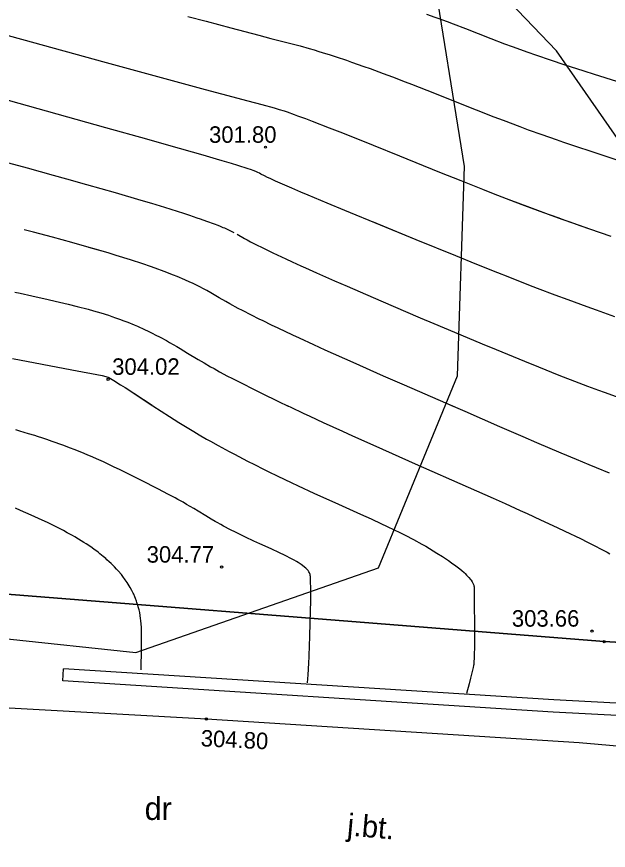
# Model space of a CAD drawing. Extents: x 7477803 to 7478145, y 5500698 to 5500984.
# Drawn here: x 7477958.24 to 7477982.63, y 5500809.46 to 5500843.86 of the extents above; entities that cross this region are included whole.
import ezdxf

# ---------------------------------------------------------------- set-up
doc = ezdxf.new("R2010")
doc.units = 0
for name, color, linetype in [('203-Punkt załamania granicy działki nie stabilizowany', 7, 'Continuous'), ('gr_dzialki', 7, 'Continuous'), ('gr_klasy', 7, 'Continuous'), ('jezdnia', 7, 'Continuous'), ('opis_uzytek', 7, 'Continuous'), ('opisy_drog', 7, 'Continuous'), ('pkt_wys', 7, 'Continuous'), ('rowy', 7, 'Continuous'), ('uwagi_projektanci', 7, 'Continuous'), ('warst_ciagla', 7, 'Continuous'), ('warst_pogrub', 7, 'Continuous'), ('warst_przeryw', 7, 'Continuous')]:
    doc.layers.add(name, color=color, linetype=linetype)

# ---------------------------------------------------------------- blocks, each defined once
blk = doc.blocks.new('203')
blk.add_circle((0, 0), 0.045)
blk = doc.blocks.new('801_1')
at = {"layer": 'pkt_wys'}
blk.add_circle((0, 0), 0.045, dxfattribs=at)
blk.add_circle((0, 0), 0.045, dxfattribs=at)
blk = doc.blocks.new('801_3')
at = {"layer": 'pkt_wys'}
blk.add_circle((0, 0), 0.045, dxfattribs=at)
blk.add_circle((0, 0), 0.045, dxfattribs=at)
blk = doc.blocks.new('801_5')
at = {"layer": 'pkt_wys'}
blk.add_circle((0, 0), 0.05, dxfattribs=at)
blk.add_circle((0, 0), 0.05, dxfattribs=at)

msp = doc.modelspace()

# ---------------------------------------------------------------- linework, layer by layer
at = {"layer": 'gr_dzialki'}
for points in [[(7477982.46, 5500818.07), (7477950.55, 5500820.61)], [(7478006.38, 5500816.66), (7477982.46, 5500818.07)]]:
    msp.add_lwpolyline(points, dxfattribs=at)
at = {"layer": 'gr_klasy'}
for points in [[(7477980.49, 5500842.45), (7477927.08, 5500898.2)], [(7477998.08, 5500817.16), (7477980.49, 5500842.45)], [(7477950.55, 5500820.61), (7477982.46, 5500818.07)], [(7477982.46, 5500818.07), (7477998.08, 5500817.16)]]:
    msp.add_lwpolyline(points, dxfattribs=at)
at = {"layer": 'jezdnia'}
msp.add_lwpolyline([(7477875.926, 5500787.879), (7477876.814, 5500788.851), (7477888.353, 5500798.574), (7477893.52, 5500801.94), (7477899.965, 5500805.717), (7477906.333, 5500808.394), (7477918.837, 5500813.137), (7477925.266, 5500814.534), (7477933.655, 5500815.503), (7477941.064, 5500815.881), (7477951.515, 5500815.693), (7477966.065, 5500814.879), (7477981.427, 5500813.916), (7477996.758, 5500812.562), (7478008.149, 5500811.845)], dxfattribs=at)
at = {"layer": 'rowy'}
for points in [[(7477990.382, 5500814.641), (7477980.361, 5500815.165), (7477960.146, 5500816.452), (7477960.178, 5500816.951)], [(7477990.411, 5500815.14), (7477980.39, 5500815.664), (7477960.178, 5500816.951)]]:
    msp.add_lwpolyline(points, dxfattribs=at)
at = {"layer": 'uwagi_projektanci'}
msp.add_lwpolyline([(7477973.16, 5500821.11), (7477976.42, 5500829.04), (7477976.7, 5500837.68), (7477975.34, 5500846.14), (7477969.75, 5500849.6), (7477966.4, 5500846.83), (7477944.18, 5500852.96), (7477931.39, 5500854.5), (7477929.49, 5500844.63), (7477930.21, 5500832.13), (7477946.85, 5500819.35), (7477963.16, 5500817.62)], close=True, dxfattribs=at)
at = {"layer": 'warst_ciagla'}
for points in [[(7477965.304, 5500843.867), (7477966.053, 5500843.666), (7477967.068, 5500843.396), (7477968.222, 5500843.092), (7477968.714, 5500842.964), (7477969.549, 5500842.749), (7477969.928, 5500842.648), (7477970.305, 5500842.543), (7477970.5, 5500842.486), (7477970.7, 5500842.426), (7477970.979, 5500842.34), (7477971.122, 5500842.294), (7477971.418, 5500842.198), (7477971.832, 5500842.059), (7477972.047, 5500841.985), (7477972.549, 5500841.808), (7477972.811, 5500841.714), (7477973.17, 5500841.582), (7477973.354, 5500841.514), (7477973.732, 5500841.373), (7477974.254, 5500841.174), (7477974.523, 5500841.069), (7477975.147, 5500840.824), (7477977.183, 5500840.013), (7477977.915, 5500839.727), (7477978.291, 5500839.583), (7477978.978, 5500839.325), (7477979.335, 5500839.195), (7477979.891, 5500838.994), (7477980.48, 5500838.787), (7477980.789, 5500838.68), (7477981.439, 5500838.459), (7477981.782, 5500838.344), (7477982.322, 5500838.165), (7477983.358, 5500837.827)], [(7477982.895, 5500831.478), (7477982.144, 5500831.744), (7477981.761, 5500831.882), (7477981.242, 5500832.072), (7477980.979, 5500832.169), (7477980.446, 5500832.368), (7477979.72, 5500832.644), (7477979.352, 5500832.786), (7477978.507, 5500833.117), (7477978.077, 5500833.287), (7477977.211, 5500833.634), (7477976.348, 5500833.984), (7477974.706, 5500834.656), (7477971.769, 5500835.866), (7477971.039, 5500836.169), (7477970.26, 5500836.494), (7477969.953, 5500836.623), (7477969.591, 5500836.777), (7477969.102, 5500836.99), (7477968.911, 5500837.077), (7477968.686, 5500837.18), (7477968.588, 5500837.226), (7477968.456, 5500837.29), (7477968.312, 5500837.363), (7477968.254, 5500837.395), (7477968.181, 5500837.434), (7477968.135, 5500837.456), (7477968.038, 5500837.496), (7477967.887, 5500837.55), (7477967.785, 5500837.584), (7477967.355, 5500837.719), (7477967.103, 5500837.795), (7477966.708, 5500837.913), (7477966.486, 5500837.978), (7477965.926, 5500838.141), (7477964.513, 5500838.547), (7477963.608, 5500838.803), (7477961.921, 5500839.278), (7477957.904, 5500840.402)], [(7477982.895, 5500831.478), (7477982.144, 5500831.744), (7477981.761, 5500831.882), (7477981.242, 5500832.072), (7477980.979, 5500832.169), (7477980.446, 5500832.368), (7477979.72, 5500832.644), (7477979.352, 5500832.786), (7477978.507, 5500833.117), (7477978.077, 5500833.287), (7477977.211, 5500833.634), (7477976.348, 5500833.984), (7477974.706, 5500834.656), (7477972.95, 5500835.378)], [(7477976.282, 5500827.755), (7477975.934, 5500827.906), (7477974.235, 5500828.648), (7477973.369, 5500829.029), (7477972.113, 5500829.585), (7477970.965, 5500830.102), (7477970.493, 5500830.318), (7477969.9, 5500830.591), (7477969.62, 5500830.721), (7477969.028, 5500831.001), (7477968.752, 5500831.134), (7477968.404, 5500831.302), (7477968.239, 5500831.383), (7477967.928, 5500831.539), (7477967.549, 5500831.732), (7477967.375, 5500831.823), (7477967.023, 5500832.013), (7477966.866, 5500832.1), (7477966.584, 5500832.263), (7477966.245, 5500832.461), (7477966.079, 5500832.555), (7477965.909, 5500832.648), (7477965.821, 5500832.695), (7477965.682, 5500832.765), (7477965.486, 5500832.86), (7477965.384, 5500832.907), (7477965.169, 5500833.003), (7477964.863, 5500833.133), (7477964.701, 5500833.198), (7477964.317, 5500833.347), (7477963.95, 5500833.482), (7477963.754, 5500833.551), (7477963.443, 5500833.657), (7477962.927, 5500833.826), (7477962.338, 5500834.009), (7477962.012, 5500834.107), (7477961.379, 5500834.293), (7477961.043, 5500834.39), (7477960.521, 5500834.537), (7477959.722, 5500834.756), (7477958.935, 5500834.965), (7477958.556, 5500835.063)], [(7477982.683, 5500825.027), (7477982.143, 5500825.244), (7477981.841, 5500825.368), (7477981.32, 5500825.586), (7477980.695, 5500825.851), (7477979.692, 5500826.279), (7477979.118, 5500826.526), (7477978.166, 5500826.937), (7477976.727, 5500827.562), (7477975.934, 5500827.906), (7477974.235, 5500828.648), (7477973.369, 5500829.029), (7477972.113, 5500829.585), (7477970.965, 5500830.102), (7477970.493, 5500830.318), (7477969.9, 5500830.591), (7477969.62, 5500830.721), (7477969.028, 5500831.001), (7477968.752, 5500831.134), (7477968.404, 5500831.302), (7477968.239, 5500831.383), (7477967.928, 5500831.539), (7477967.549, 5500831.732), (7477967.375, 5500831.823), (7477967.023, 5500832.013), (7477966.866, 5500832.1), (7477966.584, 5500832.263), (7477966.245, 5500832.461), (7477966.079, 5500832.555), (7477965.909, 5500832.648), (7477965.821, 5500832.695), (7477965.682, 5500832.765), (7477965.486, 5500832.86), (7477965.384, 5500832.907), (7477965.169, 5500833.003), (7477964.863, 5500833.133), (7477964.701, 5500833.198), (7477964.317, 5500833.347), (7477963.95, 5500833.482), (7477963.754, 5500833.551), (7477963.443, 5500833.657), (7477962.927, 5500833.826), (7477962.338, 5500834.009), (7477962.012, 5500834.107), (7477961.218, 5500834.339)], [(7477958.075, 5500829.751), (7477960.518, 5500829.287), (7477961.765, 5500829.047), (7477961.913, 5500829.017), (7477961.961, 5500829.004), (7477962.019, 5500828.983), (7477962.046, 5500828.97), (7477962.108, 5500828.934), (7477962.247, 5500828.848), (7477962.527, 5500828.67), (7477962.708, 5500828.553), (7477963.857, 5500827.806), (7477964.542, 5500827.36), (7477964.925, 5500827.118), (7477965.334, 5500826.865), (7477965.548, 5500826.737), (7477965.769, 5500826.607), (7477966.072, 5500826.431), (7477966.229, 5500826.343), (7477966.55, 5500826.164), (7477966.995, 5500825.922), (7477967.226, 5500825.8), (7477967.763, 5500825.521), (7477968.041, 5500825.38), (7477968.421, 5500825.189), (7477968.616, 5500825.093), (7477969.014, 5500824.899), (7477969.562, 5500824.637), (7477969.843, 5500824.505), (7477970.495, 5500824.203), (7477971.512, 5500823.743), (7477972.417, 5500823.335), (7477972.857, 5500823.134), (7477973.281, 5500822.937), (7477973.486, 5500822.84), (7477973.837, 5500822.671), (7477974.006, 5500822.588), (7477974.252, 5500822.464), (7477974.605, 5500822.28), (7477974.941, 5500822.098), (7477975.103, 5500822.006), (7477975.417, 5500821.821), (7477975.569, 5500821.728), (7477975.792, 5500821.586), (7477976.048, 5500821.415), (7477976.171, 5500821.329), (7477976.347, 5500821.199), (7477976.511, 5500821.069), (7477976.588, 5500821.005), (7477976.684, 5500820.92), (7477976.729, 5500820.878), (7477976.792, 5500820.815), (7477976.879, 5500820.722), (7477976.945, 5500820.641), (7477976.974, 5500820.601), (7477977.013, 5500820.542), (7477977.046, 5500820.485), (7477977.06, 5500820.457), (7477977.082, 5500820.401), (7477977.09, 5500820.374), (7477977.1, 5500820.333)], [(7477958.075, 5500829.751), (7477960.518, 5500829.287), (7477961.765, 5500829.047), (7477961.913, 5500829.017), (7477961.961, 5500829.004), (7477962.019, 5500828.983), (7477962.046, 5500828.97), (7477962.108, 5500828.934), (7477962.247, 5500828.848), (7477962.527, 5500828.67), (7477962.708, 5500828.553), (7477963.832, 5500827.822)], [(7477977.1, 5500820.333), (7477977.109, 5500819.435), (7477977.112, 5500818.942), (7477977.114, 5500818.179), (7477977.113, 5500817.894), (7477977.106, 5500817.482), (7477977.102, 5500817.384), (7477977.094, 5500817.234), (7477977.084, 5500817.131), (7477977.076, 5500817.081), (7477977.059, 5500817.002), (7477976.954, 5500816.569), (7477976.892, 5500816.326), (7477976.792, 5500815.937)]]:
    msp.add_lwpolyline(points, dxfattribs=at)
at = {"layer": 'warst_pogrub'}
msp.add_lwpolyline([(7477963.374, 5500816.904), (7477963.375, 5500817.164), (7477963.381, 5500817.542), (7477963.385, 5500817.745), (7477963.393, 5500818.195), (7477963.391, 5500818.43), (7477963.383, 5500818.668), (7477963.375, 5500818.789), (7477963.36, 5500818.949), (7477963.35, 5500819.029), (7477963.333, 5500819.149), (7477963.312, 5500819.268), (7477963.299, 5500819.327), (7477963.286, 5500819.386), (7477963.267, 5500819.465), (7477963.256, 5500819.504), (7477963.234, 5500819.582), (7477963.201, 5500819.684), (7477963.183, 5500819.736), (7477963.14, 5500819.85), (7477963.109, 5500819.926), (7477963.065, 5500820.026), (7477963.041, 5500820.076), (7477962.992, 5500820.175), (7477962.92, 5500820.306), (7477962.882, 5500820.371), (7477962.79, 5500820.516), (7477962.717, 5500820.623), (7477962.612, 5500820.765), (7477962.556, 5500820.835), (7477962.424, 5500820.992), (7477962.363, 5500821.06), (7477962.277, 5500821.152), (7477962.233, 5500821.197), (7477962.131, 5500821.298), (7477962.061, 5500821.365), (7477961.963, 5500821.453), (7477961.914, 5500821.497), (7477961.811, 5500821.584), (7477961.67, 5500821.699), (7477961.596, 5500821.756), (7477961.426, 5500821.883), (7477961.293, 5500821.977), (7477961.109, 5500822.101), (7477961.015, 5500822.163), (7477960.794, 5500822.299), (7477960.642, 5500822.389), (7477960.539, 5500822.448), (7477960.329, 5500822.564), (7477960.169, 5500822.651), (7477959.842, 5500822.819), (7477959.51, 5500822.983), (7477959.287, 5500823.089), (7477958.843, 5500823.294), (7477958.404, 5500823.488), (7477958.186, 5500823.582)], dxfattribs=at)
at = {"layer": 'warst_przeryw'}
for points in [[(7477982.978, 5500841.179), (7477982.067, 5500841.466), (7477981.632, 5500841.605), (7477981.076, 5500841.786), (7477980.807, 5500841.875), (7477980.289, 5500842.048), (7477979.638, 5500842.271), (7477979.33, 5500842.379), (7477978.677, 5500842.613), (7477978.373, 5500842.726), (7477977.8, 5500842.944), (7477976.752, 5500843.352), (7477976.25, 5500843.546), (7477975.999, 5500843.641), (7477975.662, 5500843.765), (7477975.493, 5500843.827), (7477975.155, 5500843.948)], [(7477982.744, 5500834.785), (7477981.875, 5500835.084), (7477981.439, 5500835.237), (7477980.855, 5500835.446), (7477980.563, 5500835.551), (7477979.976, 5500835.766), (7477979.19, 5500836.059), (7477978.795, 5500836.209), (7477977.904, 5500836.553), (7477977.457, 5500836.728), (7477976.566, 5500837.082), (7477975.691, 5500837.435), (7477974.044, 5500838.103), (7477972.947, 5500838.546), (7477971.687, 5500839.048), (7477971.143, 5500839.262), (7477970.435, 5500839.535), (7477970.163, 5500839.638), (7477969.839, 5500839.758), (7477969.694, 5500839.811), (7477969.41, 5500839.911), (7477969.289, 5500839.952), (7477969.075, 5500840.02), (7477968.869, 5500840.08), (7477968.358, 5500840.217), (7477967.779, 5500840.372), (7477966.701, 5500840.662), (7477966.032, 5500840.844), (7477961.942, 5500841.958), (7477956.699, 5500843.391)], [(7477957.903, 5500837.826), (7477958.667, 5500837.618), (7477959.743, 5500837.322), (7477960.293, 5500837.169), (7477961.115, 5500836.938), (7477962.297, 5500836.6), (7477963.366, 5500836.287), (7477963.8, 5500836.157), (7477964.339, 5500835.992), (7477964.592, 5500835.913), (7477965.121, 5500835.744), (7477965.364, 5500835.665), (7477965.667, 5500835.563), (7477965.809, 5500835.515), (7477966.073, 5500835.422), (7477966.388, 5500835.306), (7477966.528, 5500835.252), (7477966.626, 5500835.213), (7477966.747, 5500835.163), (7477966.803, 5500835.139), (7477966.948, 5500835.075), (7477967.034, 5500835.033), (7477967.189, 5500834.955)], [(7477982.744, 5500834.785), (7477981.875, 5500835.084), (7477981.508, 5500835.213), (7477981.017, 5500835.388), (7477980.771, 5500835.476), (7477980.278, 5500835.655), (7477979.618, 5500835.899), (7477979.287, 5500836.023), (7477978.539, 5500836.307)], [(7477967.326, 5500834.88), (7477967.638, 5500834.704), (7477967.737, 5500834.65), (7477967.881, 5500834.573), (7477967.958, 5500834.533), (7477968.123, 5500834.449), (7477968.364, 5500834.329), (7477968.493, 5500834.265), (7477968.808, 5500834.114), (7477969.338, 5500833.865), (7477969.596, 5500833.746), (7477969.961, 5500833.579), (7477970.153, 5500833.492), (7477970.607, 5500833.288), (7477971.344, 5500832.962), (7477971.863, 5500832.734), (7477972.944, 5500832.265), (7477973.769, 5500831.909), (7477974.882, 5500831.434), (7477975.443, 5500831.196), (7477976.292, 5500830.839), (7477977.436, 5500830.361), (7477978.013, 5500830.121), (7477979.172, 5500829.644), (7477979.748, 5500829.41), (7477980.595, 5500829.072), (7477981.414, 5500828.753), (7477981.768, 5500828.618), (7477982.231, 5500828.445), (7477982.458, 5500828.361), (7477982.96, 5500828.179)], [(7477958.162, 5500832.49), (7477958.385, 5500832.443), (7477958.868, 5500832.339), (7477959.546, 5500832.188), (7477959.829, 5500832.123), (7477960.189, 5500832.038), (7477960.362, 5500831.996), (7477960.732, 5500831.904), (7477961.189, 5500831.785), (7477961.405, 5500831.726), (7477961.717, 5500831.635), (7477962.021, 5500831.54), (7477962.171, 5500831.49), (7477962.321, 5500831.438), (7477962.52, 5500831.365), (7477962.62, 5500831.328), (7477962.819, 5500831.25), (7477963.084, 5500831.141), (7477963.216, 5500831.084), (7477963.512, 5500830.95), (7477963.661, 5500830.881), (7477963.858, 5500830.784), (7477963.956, 5500830.735), (7477964.153, 5500830.633), (7477964.415, 5500830.493), (7477964.545, 5500830.42), (7477964.839, 5500830.251), (7477964.985, 5500830.163), (7477965.286, 5500829.98), (7477965.723, 5500829.714), (7477965.967, 5500829.569), (7477966.234, 5500829.415), (7477966.377, 5500829.335), (7477966.606, 5500829.208), (7477966.937, 5500829.031), (7477967.114, 5500828.938), (7477967.49, 5500828.744), (7477968.037, 5500828.469), (7477968.33, 5500828.324), (7477969.038, 5500827.98), (7477969.432, 5500827.792)], [(7477969.169, 5500827.917), (7477969.539, 5500827.742), (7477970.055, 5500827.498), (7477970.324, 5500827.373), (7477970.882, 5500827.114), (7477971.668, 5500826.754), (7477972.08, 5500826.568), (7477973.05, 5500826.131), (7477974.668, 5500825.413), (7477976.859, 5500824.444), (7477977.892, 5500823.984), (7477978.379, 5500823.766), (7477978.993, 5500823.488), (7477979.286, 5500823.355), (7477979.843, 5500823.099), (7477980.524, 5500822.781), (7477980.839, 5500822.632), (7477981.485, 5500822.322), (7477981.775, 5500822.179), (7477982.128, 5500822.002), (7477982.289, 5500821.919), (7477982.584, 5500821.764), (7477982.702, 5500821.7)], [(7477970.232, 5500816.374), (7477970.255, 5500816.699), (7477970.284, 5500817.188), (7477970.297, 5500817.455), (7477970.316, 5500817.927), (7477970.328, 5500818.25), (7477970.347, 5500818.876), (7477970.357, 5500819.297), (7477970.365, 5500819.784), (7477970.367, 5500819.995), (7477970.366, 5500820.27), (7477970.36, 5500820.561), (7477970.355, 5500820.675), (7477970.348, 5500820.758), (7477970.344, 5500820.794), (7477970.335, 5500820.844), (7477970.321, 5500820.889), (7477970.313, 5500820.91), (7477970.292, 5500820.951), (7477970.279, 5500820.972), (7477970.256, 5500821.003), (7477970.228, 5500821.035), (7477970.185, 5500821.08), (7477970.16, 5500821.103), (7477970.104, 5500821.15), (7477970.018, 5500821.216), (7477969.969, 5500821.25), (7477969.847, 5500821.33), (7477969.779, 5500821.371), (7477969.681, 5500821.429), (7477969.629, 5500821.458), (7477969.519, 5500821.518), (7477969.361, 5500821.601), (7477969.276, 5500821.643), (7477969.072, 5500821.742), (7477968.736, 5500821.898), (7477968.26, 5500822.113), (7477968.022, 5500822.221), (7477967.681, 5500822.38), (7477967.536, 5500822.45), (7477967.348, 5500822.541), (7477967.256, 5500822.587), (7477967.057, 5500822.688), (7477966.774, 5500822.837), (7477966.654, 5500822.901), (7477966.501, 5500822.987), (7477966.427, 5500823.029), (7477966.266, 5500823.123), (7477966.038, 5500823.263), (7477965.724, 5500823.457), (7477965.549, 5500823.563), (7477965.248, 5500823.736), (7477965.099, 5500823.82), (7477964.886, 5500823.937), (7477964.773, 5500823.999), (7477964.504, 5500824.143), (7477964.06, 5500824.376), (7477963.394, 5500824.716), (7477963.03, 5500824.9), (7477962.511, 5500825.156), (7477962.239, 5500825.288), (7477961.817, 5500825.486), (7477961.526, 5500825.618), (7477961.378, 5500825.683), (7477961.154, 5500825.779), (7477960.926, 5500825.874), (7477960.617, 5500825.998), (7477960.46, 5500826.059), (7477960.142, 5500826.179), (7477959.709, 5500826.333), (7477959.488, 5500826.408), (7477959.321, 5500826.463), (7477959.096, 5500826.536), (7477958.983, 5500826.572), (7477958.725, 5500826.651), (7477958.377, 5500826.755), (7477958.2, 5500826.805)]]:
    msp.add_lwpolyline(points, dxfattribs=at)

# ---------------------------------------------------------------- block references
at = {"layer": '203-Punkt załamania granicy działki nie stabilizowany'}
msp.add_blockref('203', (7477982.46, 5500818.07), dxfattribs=at)
at = {"layer": 'pkt_wys', "rotation": 0.0626175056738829}
for name, p in [('801_3', (7477968.5, 5500838.471)), ('801_1', (7477962.01, 5500828.894)), ('801_1', (7477966.689, 5500821.149)), ('801_1', (7477981.962, 5500818.506)), ('801_5', (7477966.065, 5500814.879))]:
    msp.add_blockref(name, p, dxfattribs=at)

# ---------------------------------------------------------------- texts
at = {"layer": 'opis_uzytek'}
msp.add_text('dr', height=0.94, dxfattribs=at).set_placement((7477963.519, 5500810.714))
at = {"layer": 'opisy_drog'}
msp.add_text('j.bt.', height=0.9, rotation=354.8823, dxfattribs=at).set_placement((7477971.842, 5500810.079))
at = {"layer": 'pkt_wys'}
for s, rotation, p in [('301.80', 0.0626, (7477966.172, 5500838.653)), ('304.02', 0.0626, (7477962.179, 5500829.079)), ('304.77', 0.0626, (7477963.601, 5500821.33)), ('303.66', 0.0626, (7477978.657, 5500818.687)), ('304.80', 357.362, (7477965.819, 5500813.753))]:
    msp.add_text(s, height=0.68, rotation=rotation, dxfattribs=at).set_placement(p)

doc.saveas('drawing.dxf')
